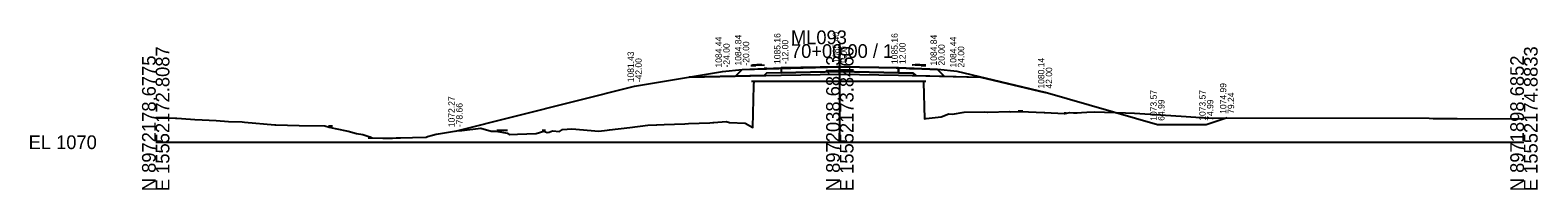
# Model space of a CAD drawing. Extents: x -26 to 14283, y -10 to 28.
# Drawn here: x 7974.3 to 8282.8, y -9.7 to 22.8 of the extents above; entities that cross this region are included whole.
import ezdxf

# ---------------------------------------------------------------- set-up
doc = ezdxf.new("R2010")
doc.units = 0
for name, color, linetype in [('Default', 7, 'Continuous'), ('dsn3DCenterLine', 7, 'Continuous'), ('dsn3DDitchBack', 7, 'Continuous'), ('dsn3DDitchFront', 7, 'Continuous'), ('dsn3DForeSlopeBarnRoofPoint', 7, 'Continuous'), ('dsn3DForeSlopeBreakLine', 7, 'Continuous'), ('dsn3DGroundLineIntercept', 7, 'Continuous'), ('dsn3DPavementTop', 7, 'Continuous'), ('dsn3DShoulderTop', 7, 'Continuous'), ('dsn3DSubgradeBreakLine', 7, 'Continuous'), ('dsn3DSubgradeHingePoint', 7, 'Continuous'), ('dsnGeopakCellCrossSection', 7, 'Continuous'), ('dsnXSEarthwork', 7, 'Continuous'), ('dsnXsExistingGround', 7, 'Continuous'), ('dsnXsPCCPavement', 7, 'Continuous'), ('dsnXsShldrEarthFill', 7, 'Continuous'), ('dsnXsShldrGranular', 7, 'Continuous'), ('dsnXsSideSlopes', 7, 'Continuous'), ('dsnXsSubbase', 7, 'Continuous'), ('dsnXsTextOffsetElevFinGrd', 7, 'Continuous'), ('SurBridge', 7, 'Continuous'), ('SurConcreteSlab', 7, 'Continuous'), ('SurDrainage', 7, 'Continuous'), ('SurPointsNonDTM', 7, 'Continuous'), ('SurSurveyPoints', 7, 'Continuous')]:
    doc.layers.add(name, color=color, linetype=linetype)

msp = doc.modelspace()

# ---------------------------------------------------------------- linework, layer by layer
at = {"layer": 'Default'}
for points in [[(8109.16, 13.3), (8109.16, 13.3), (8128, 13.66), (8140, 13.9), (8152, 13.66), (8168.78, 13.3), (8182, 10.14)], [(8120, 14.84), (8140, 15.4), (8152, 15.16), (8160, 14.84)]]:
    msp.add_lwpolyline(points, dxfattribs=at)
at = {"layer": 'dsnGeopakCellCrossSection'}
for p, q in [((8140, 0), (8140, 20)), ((8000, 0), (8140, 0)), ((8140, 0), (8280, 0))]:
    msp.add_line(p, q, dxfattribs=at)
at = {"layer": 'dsnXSEarthwork'}
msp.add_lwpolyline([(8120, 14.84), (8128, 15.16), (8140, 15.4), (8152, 15.16), (8160, 14.84)], dxfattribs=at)
at = {"layer": 'dsnXsExistingGround'}
msp.add_lwpolyline([(8000, 5), (8004.07, 4.94), (8004.34, 4.92), (8007.1, 4.7), (8008.02, 4.66), (8009.53, 4.6), (8012.37, 4.41), (8014.93, 4.24), (8017.67, 4.15), (8018.15, 4.11), (8024.37, 3.55), (8024.42, 3.55), (8024.54, 3.54), (8024.57, 3.53), (8029.39, 3.43), (8034.59, 3.32), (8034.6, 3.32), (8034.64, 3.32), (8035.5, 3.07), (8036.71, 2.79), (8039.41, 2.25), (8041.09, 1.77), (8042.38, 1.58), (8043.83, 1.12), (8043.84, 1.11), (8043.88, 1.09), (8044.27, 0.89), (8046.5, 0.86), (8048.44, 0.86), (8049.24, 0.89), (8050.09, 0.91), (8052.56, 0.99), (8055.36, 1.06), (8055.6, 1.18), (8056.61, 1.43), (8057.4, 1.66), (8057.85, 1.74), (8061.97, 2.36), (8062.67, 2.38), (8066.54, 2.89), (8068.67, 2.26), (8069.62, 2.29), (8071.96, 1.86), (8072.5, 1.61), (8074.04, 1.64), (8077.87, 1.81), (8079.41, 2.27), (8080.09, 2), (8080.52, 2.08), (8081.18, 2.3), (8081.19, 2.3), (8082.61, 2.22), (8083.22, 2.59), (8085.16, 2.7), (8090.65, 2.28), (8092.41, 2.49), (8092.88, 2.55), (8097, 3.03), (8100.71, 3.48), (8102.52, 3.56), (8102.58, 3.57), (8104.04, 3.64), (8108.29, 3.78), (8109.02, 3.81), (8113.43, 3.96), (8114.03, 4.03), (8114.19, 4.02), (8116.73, 4.2), (8117.44, 4.05), (8120.66, 3.91), (8122.21, 3.01), (8122.43, 11.6), (8122.46, 12.48), (8122.7, 12.48), (8127.27, 12.48), (8127.67, 12.48), (8132.28, 12.48), (8132.64, 12.48), (8137.29, 12.48), (8137.61, 12.48), (8142.3, 12.48), (8142.58, 12.48), (8147.31, 12.48), (8147.55, 12.48), (8152.32, 12.48), (8152.51, 12.48), (8157.08, 12.48), (8157.09, 12.25), (8157.34, 4.76), (8157.65, 4.83), (8160.73, 5.15), (8162.29, 5.76), (8163.05, 5.75), (8165.42, 6.1), (8169.55, 6.17), (8170.21, 6.16), (8170.29, 6.15), (8174.74, 6.24), (8174.99, 6.21), (8176.95, 6.27), (8176.95, 6.27), (8181.8, 6.04), (8181.94, 6.05), (8185.94, 5.86), (8186.13, 5.87), (8187.05, 6.08), (8188.58, 6.01), (8189.45, 6.07), (8190.52, 6.15), (8192.03, 6.18), (8198.49, 6.02), (8200.3, 5.93), (8209.82, 5.31), (8212.86, 5.12), (8213.64, 5.07), (8214.15, 5.04), (8214.28, 5.03), (8214.63, 5.01), (8214.89, 5), (8260.58, 4.88), (8261.42, 4.86), (8263.25, 4.83), (8263.78, 4.83), (8266.36, 4.83), (8280, 4.76)], dxfattribs=at)
at = {"layer": 'dsnXsPCCPavement'}
msp.add_lwpolyline([(8128, 15.16), (8128, 15.16), (8128, 14.16), (8128, 14.16), (8128, 14.16), (8140, 14.4), (8152, 14.16), (8152, 14.16), (8152, 14.16), (8152, 15.16), (8152, 15.16), (8140, 15.4), (8128, 15.16)], dxfattribs=at)
at = {"layer": 'dsnXsShldrEarthFill'}
for points in [[(8118.64, 13.48), (8109.16, 13.3)], [(8161.38, 13.45), (8168.78, 13.3)]]:
    msp.add_lwpolyline(points, dxfattribs=at)
at = {"layer": 'dsnXsShldrGranular'}
for points in [[(8120, 14.84), (8128, 15.16), (8128, 14.16), (8128, 14.16), (8125, 14.1), (8125, 14.1), (8124.49, 13.59), (8124.49, 13.59), (8118.64, 13.48), (8118.64, 13.48), (8118.64, 13.48), (8120, 14.84), (8120, 14.84)], [(8160, 14.84), (8152, 15.16), (8152, 14.16), (8152, 14.16), (8155, 14.1), (8155, 14.1), (8155.52, 13.58), (8155.52, 13.58), (8161.38, 13.45), (8161.38, 13.45), (8161.38, 13.45), (8160, 14.84), (8160, 14.84)]]:
    msp.add_lwpolyline(points, dxfattribs=at)
at = {"layer": 'dsnXsSideSlopes'}
for points in [[(8061.34, 2.27), (8098, 11.43), (8098, 11.43), (8098, 11.43), (8116, 14.44), (8116, 14.44), (8120, 14.84)], [(8219.24, 4.99), (8214.99, 3.57), (8214.99, 3.57), (8204.99, 3.57), (8204.99, 3.57), (8182, 10.14), (8182, 10.14), (8182, 10.14), (8164, 14.44), (8164, 14.44), (8160, 14.84)]]:
    msp.add_lwpolyline(points, dxfattribs=at)
at = {"layer": 'dsnXsSubbase'}
msp.add_lwpolyline([(8124.49, 13.59), (8124.49, 13.59), (8124.49, 13.59), (8128, 13.66), (8128, 13.66), (8140, 13.9), (8152, 13.66), (8152, 13.66), (8155.52, 13.58), (8155.52, 13.58), (8155.52, 13.58), (8155, 14.1), (8155, 14.1), (8152, 14.16), (8152, 14.16), (8140, 14.4), (8128, 14.16), (8128, 14.16), (8125, 14.1), (8125, 14.1), (8124.49, 13.59)], dxfattribs=at)
at = {"layer": 'SurBridge'}
for points in [[(8122.3, 15.66), (8122.64, 15.76), (8122.64, 15.76), (8123.53, 15.8), (8124.57, 15.72), (8124.6, 15.71)], [(8157.14, 15.63), (8157.14, 15.63), (8155.91, 15.77), (8155.91, 15.77), (8154.86, 15.73), (8154.83, 15.73)]]:
    msp.add_lwpolyline(points, dxfattribs=at)
at = {"layer": 'SurConcreteSlab'}
msp.add_lwpolyline([(8122.46, 12.48), (8125.34, 12.48), (8157.08, 12.48)], dxfattribs=at)
at = {"layer": 'SurDrainage'}
msp.add_lwpolyline([(8069.81, 2.44), (8071.99, 2.44)], dxfattribs=at)
at = {"layer": 'SurPointsNonDTM'}
for points in [[(8121.82, 15.66), (8122.79, 15.66)], [(8122.15, 15.76), (8123.13, 15.76)], [(8124.01, 15.8), (8123.04, 15.8)], [(8155.42, 15.77), (8156.4, 15.77)], [(8156.33, 15.77), (8157.31, 15.77)], [(8156.64, 15.63), (8157.63, 15.63)], [(8125.07, 15.01), (8124.49, 15.01)], [(8139.29, 15.42), (8140.1, 15.42)], [(8154.27, 15.07), (8155.12, 15.07)]]:
    msp.add_lwpolyline(points, dxfattribs=at)
at = {"layer": 'SurSurveyPoints'}
for points in [[(8121.9, 15.72), (8122.82, 15.72)], [(8123.98, 15.75), (8123.03, 15.75)], [(8156.36, 15.77), (8155.42, 15.77)], [(8156.65, 15.76), (8157.57, 15.76)], [(8121.89, 12.48), (8122.85, 12.48)], [(8127.45, 15.13), (8128.08, 15.13)], [(8139.55, 15.42), (8140.31, 15.42)], [(8151.51, 15.16), (8152.32, 15.16)], [(8156.61, 12.48), (8157.61, 12.48)], [(8177.44, 6.33), (8176.46, 6.33)], [(8036.2, 3.3), (8035.35, 3.3)], [(8185.89, 6.03), (8186.33, 6.03)], [(8188.6, 5.96), (8187.82, 5.96)], [(8043.46, 0.89), (8044.39, 0.89)], [(8079.77, 2.38), (8079.08, 2.38)]]:
    msp.add_lwpolyline(points, dxfattribs=at)

# ---------------------------------------------------------------- texts
msp.add_text('-', height=0.0001).set_placement((8000, 0))
at = {"layer": 'dsn3DCenterLine'}
msp.add_text('X', height=0.00781, dxfattribs=at).set_placement((8140, 15.39))
at = {"layer": 'dsn3DDitchBack'}
msp.add_text('X', height=0.00781, dxfattribs=at).set_placement((8214.99, 3.56))
at = {"layer": 'dsn3DDitchFront'}
msp.add_text('X', height=0.00781, dxfattribs=at).set_placement((8204.99, 3.56))
at = {"layer": 'dsn3DForeSlopeBarnRoofPoint'}
for p in [(8098, 11.43), (8182, 10.14)]:
    msp.add_text('X', height=0.00781, dxfattribs=at).set_placement(p)
at = {"layer": 'dsn3DForeSlopeBreakLine'}
for p in [(8116, 14.43), (8164, 14.43)]:
    msp.add_text('X', height=0.00781, dxfattribs=at).set_placement(p)
at = {"layer": 'dsn3DGroundLineIntercept'}
for p in [(8219.24, 4.98), (8061.33, 2.27)]:
    msp.add_text('X', height=0.00781, dxfattribs=at).set_placement(p)
at = {"layer": 'dsn3DPavementTop'}
for p in [(8128, 15.15), (8152, 15.15)]:
    msp.add_text('X', height=0.00781, dxfattribs=at).set_placement(p)
at = {"layer": 'dsn3DShoulderTop'}
for p in [(8120, 14.83), (8160, 14.83)]:
    msp.add_text('X', height=0.00781, dxfattribs=at).set_placement(p)
at = {"layer": 'dsn3DSubgradeBreakLine'}
for p in [(8128, 13.65), (8140, 13.89), (8152, 13.65)]:
    msp.add_text('X', height=0.00781, dxfattribs=at).set_placement(p)
at = {"layer": 'dsn3DSubgradeHingePoint'}
for p in [(8109.16, 13.29), (8168.77, 13.29)]:
    msp.add_text('X', height=0.00781, dxfattribs=at).set_placement(p)
at = {"layer": 'dsnGeopakCellCrossSection'}
for s, p in [('ML093', (8130, 20)), ('70+00.00 / 1', (8130, 17.2)), ('EL 1070', (7974, -1.4))]:
    msp.add_text(s, height=2.8, dxfattribs=at).set_placement(p)
for s, p in [('E 15552172.8087', (8002.8, -10)), ('E 15552173.8460', (8142.8, -10)), ('E 15552174.8833', (8282.8, -10)), ('N 8972178.6775', (8000, -10)), ('N 8972038.6813', (8140, -10)), ('N 8971898.6852', (8280, -10))]:
    msp.add_text(s, height=2.8, rotation=90, dxfattribs=at).set_placement(p)
at = {"layer": 'dsnXsTextOffsetElevFinGrd'}
for s, p in [('1084.84', (8119.85, 15.64)), ('1084.84', (8119.85, 15.64)), ('1085.16', (8127.85, 15.96)), ('1085.16', (8127.85, 15.96)), ('1085.40', (8139.85, 16.2)), ('1085.16', (8151.85, 15.96)), ('1085.16', (8151.85, 15.96)), ('1084.84', (8159.85, 15.64)), ('1084.44', (8115.85, 15.24)), ('-24.00', (8117.45, 15.24)), ('-20.00', (8121.45, 15.64)), ('-20.00', (8121.45, 15.64)), ('-12.00', (8129.45, 15.96)), ('-12.00', (8129.45, 15.96)), ('0.00', (8141.45, 16.2)), ('12.00', (8153.45, 15.96)), ('12.00', (8153.45, 15.96)), ('20.00', (8161.45, 15.64)), ('1084.44', (8163.85, 15.24)), ('24.00', (8165.45, 15.24)), ('1081.43', (8097.85, 12.23)), ('-42.00', (8099.45, 12.23)), ('1080.14', (8181.85, 10.94)), ('42.00', (8183.45, 10.94)), ('1072.27', (8061.19, 3.07)), ('1073.57', (8204.84, 4.37)), ('1073.57', (8214.84, 4.37)), ('1074.99', (8219.09, 5.79)), ('1074.99', (8219.09, 5.79)), ('79.24', (8220.69, 5.79)), ('79.24', (8220.69, 5.79)), ('-78.66', (8062.79, 3.07)), ('64.99', (8206.44, 4.37)), ('74.99', (8216.44, 4.37))]:
    msp.add_text(s, height=1.3, rotation=90, dxfattribs=at).set_placement(p)

doc.saveas('drawing.dxf')
